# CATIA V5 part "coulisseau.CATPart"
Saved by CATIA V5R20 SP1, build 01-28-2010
Part number: coulisseau
Bounding box of the stored display mesh (mm): x -30 to 0, y -200 to 600, z -15 to 15
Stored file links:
  C:\Users\Fabien-port\Desktop\test\coulisseau.CATPart
  C:\Users\Fabien-port\Desktop\test\mecanisme_a_coulisseau.CATProduct
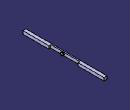
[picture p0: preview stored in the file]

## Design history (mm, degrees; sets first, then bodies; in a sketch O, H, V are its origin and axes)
External parameters (linked from other documents)
  External.cote_coulisseau = 30 mm
  External.longueur_guidage_coulisseau = 400 mm
  External.longueur_bielle3 = 80 mm
  External.epaisseur_bielle = 8 mm
  External.rayon_cylindre_bielle = 10 mm
Set1
  Plane1 "Plan_construction_coulisseau": linked copy from another document
  Point1 "Point_ref": linked copy from another document
  Plane2 "Plan_ref": linked copy from another document
  Point2 "Pt_milieu_coulisseau": linked copy from another document
  Plane3 "Plan_ref": linked copy from another document
  Point3 "Point_projete": linked copy from another document
Body1 (main body)
  Sketch1 on Plane1, origin (0, 200, 0), H (-1, 0, 0), V (0, 0, 1)
    point P1 (0, 15)
    line L1 (0, 15) -> (30, 15)
    line L2 (30, 15) -> (30, -15)
    line L3 (30, -15) -> (0, -15)
    line L4 (0, -15) -> (0, 15)
    reference projected point E1 (0, 0) from Point1
    reference projected point E2 (0, 0) from Point1
    distance L1 E1 = 15 {= External.cote_coulisseau /2}
    distance L3 E2 = 15 {= External.cote_coulisseau /2}
    length L3 = 30 {= External.cote_coulisseau}
    coincidence: P1 V
    horizontal: L1 H, L3 H
    vertical: L2 V, L4 V
  Pad1: profile Sketch1, direction (0, 1, 0), length 400 {= External.longueur_guidage_coulisseau /2+200mm}, mirrored extent
  Sketch2 on Plane2, origin (0, 0, 0), H (0, 1, 0), V (0, 0, 1)
    line L1 (56, 15) -> (344, 15)
    line L2 (344, 15) -> (344, -15)
    line L3 (344, -15) -> (56, -15)
    line L4 (56, -15) -> (56, 15)
    reference projected point E1 (200, 0) from Point2
    reference projected point E2 (200, 0) from Point2
    length L4 = 30 {= External.cote_coulisseau}
    distance L4 E1 = 144 {= External.longueur_bielle3 +0.16*External.longueur_guidage_coulisseau}
    distance L1 E2 = 15 {= External.cote_coulisseau /2}
    length L3 = 288 {= 2*External.longueur_bielle3 +2*0.16*External.longueur_guidage_coulisseau}
    horizontal: L1 H, L3 H
    vertical: L2 V, L4 V
  Pocket1: profile Sketch2, direction (-1, 0, 0), length 18 {= 2*External.epaisseur_bielle +2mm}
  Sketch3 on end face of Pocket1, origin (-18, 0, 0), H (0, 1, 0), V (0, 0, 1)
    circle A1 centre (175.838, 0) radius 15
    point P1 (175.838, 0)
    reference projected point E1 (175.838, 0) from Point3
    radius A1 = 15 {= External.cote_coulisseau /2}
    distance P1 E1 = 0
  Pad2: profile Sketch3, direction (1, 0, 0), length 1
  Sketch4 on end face of Pad2, origin (-17, 0, 0), H (0, 1, 0), V (0, 0, 1)
    circle A1 centre (175.838, 0) radius 10
    point P1 (175.838, 0)
    reference projected point E1 (175.838, 0) from Point3
    distance P1 E1 = 0
    radius A1 = 10 {= External.rayon_cylindre_bielle}
  Pad3: profile Sketch4, direction (1, 0, 0), length 8 {= External.epaisseur_bielle}
  Sketch5 on end face of Pad3, origin (-9, 0, 0), H (0, 1, 0), V (0, 0, 1)
    circle A1 centre (175.838, 0) radius 15
    point P1 (175.838, 0)
    reference projected point E1 (175.838, 0) from Point3
    distance P1 E1 = 0
    radius A1 = 15 {= External.cote_coulisseau /2}
  Pad4: profile Sketch5, direction (1, 0, 0), length 1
